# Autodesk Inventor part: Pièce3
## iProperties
Shininess: 64.0
Length Units: 11269
Angle Units: 11279
Time Units: 11290
Mass Units: 11283
Length Display Precision: 3
Angle Display Precision: 2
Compacted: True
Part Number: Pièce3
Document SubType Name: Modeling
Created: 2004-06
Material: Par défaut
Designer: administrateur
Density: 0.0
Volumn: 0.0
Area: 0.0
PropertySet Name: Model Information
Control State: 0
Master: False
Checked Out: False
Author: administrateur
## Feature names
1. Extrusion1
2. Balayage1
3. Balayage2
4. Réseau rectangulaire1 [Rectangular Pattern]
